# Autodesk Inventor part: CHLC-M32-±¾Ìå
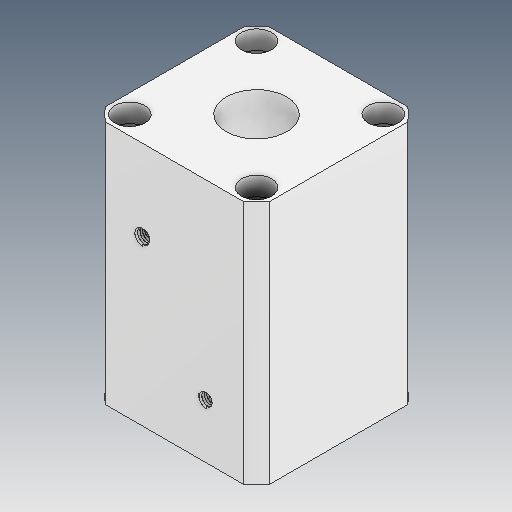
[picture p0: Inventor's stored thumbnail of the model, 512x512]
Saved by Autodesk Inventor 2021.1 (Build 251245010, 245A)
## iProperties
Created: 2021-05
Part Number: CHLC-M32-±¾Ìå
Material: Ogólny
Document SubType Name: Modeling
Designer: user
Density: 1 g/cm^3
Appearance: Domyślna
Author: user
Revision Number: ÈÎºÎ
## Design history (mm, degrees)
feature "ÇÐ³ý-À­Éì2"
node "Bryła1"
